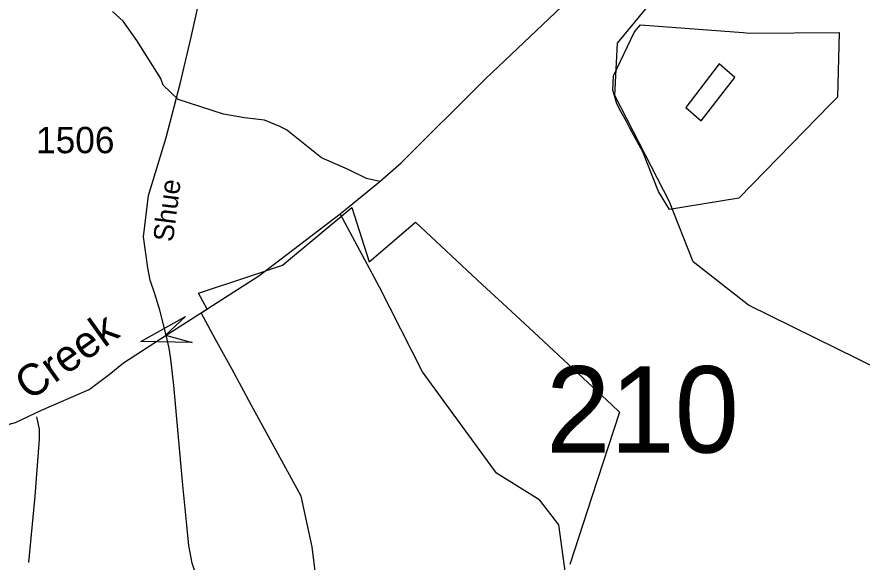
# Model space of a CAD drawing. Extents: x 1473865 to 1648260, y 639067 to 773536.
# Drawn here: x 1530604 to 1534612, y 672827 to 675414 of the extents above; entities that cross this region are included whole.
import ezdxf

# ---------------------------------------------------------------- set-up
doc = ezdxf.new("R2010")
doc.units = 0
for name, color, linetype in [('Exist Boundary Political City Limit New', 7, 'Continuous'), ('Exist Hydrographic Creek Single Shore', 7, 'Continuous'), ('Exist Hydrographic Creek Single Shore Label', 7, 'Continuous'), ('Exist Hydrographic Misc Water Feature', 7, 'Continuous'), ('Exist Road Secondary Structure Standard Bridge Attributed CELL', 7, 'Continuous'), ('Exist Road Secondary Structure Standard Bridge Number Label', 7, 'Continuous'), ('Exist Road Secondary Type 51 Attributed', 7, 'Continuous'), ('Exist Road Secondary Type 51 Label', 7, 'Continuous'), ('Exist Road Secondary Type 51 Number Label', 7, 'Continuous'), ('Map Preparation Boundary City Limit Buffer Line', 7, 'Continuous')]:
    doc.layers.add(name, color=color, linetype=linetype)

msp = doc.modelspace()

# ---------------------------------------------------------------- linework, layer by layer
at = {"layer": 'Exist Boundary Political City Limit New'}
for points in [[(1534047.8, 675339.3), (1534078, 675337.1), (1534503.1, 675340.2), (1534494.9, 675033), (1534462.8, 675000.2), (1534028.4, 674554), (1533698.5, 674499.2), (1533681.5, 674527.8), (1533646.9, 674585.9), (1533571.8, 674773.6), (1533511, 674885.8), (1533494.2, 674917), (1533468.6, 674965.2), (1533449.4, 675001.2), (1533439, 675034.2), (1533429.5, 675065.4), (1533433.9, 675133.3), (1533532.8, 675342.1), (1533560.8, 675376.4), (1534047.8, 675339.3)], [(1532025, 672732.6), (1532004, 672899.2), (1531952, 673140), (1531715.5, 673573.2), (1531622.6, 673743.5), (1531544.8, 673886.2), (1531477.8, 674009), (1531506, 674026.8), (1531464.4, 674102), (1531699.6, 674180.7), (1531862.9, 674235.2), (1532192.4, 674509.6), (1532203.5, 674474.8)], [(1532203.5, 674474.8), (1532274.9, 674251.9), (1532494.1, 674439.3), (1532812.6, 674142.9), (1532906.4, 674055.7), (1533054.9, 673917.5), (1533264.9, 673722), (1533425.1, 673572.8), (1533462, 673538.6), (1533330.9, 673135.7), (1533226.8, 672815.9)]]:
    msp.add_lwpolyline(points, dxfattribs=at)
at = {"layer": 'Exist Hydrographic Creek Single Shore'}
for points in [[(1532325.2, 674632.6), (1532425.5, 674721.4), (1532826.6, 675120.4), (1533307.6, 675577.9), (1533484, 675750.6), (1533742.1, 676058.2), (1534037.2, 676387.9), (1534170, 676555.2)], [(1530238.2, 673391.2), (1530597.9, 673489.3), (1530720.8, 673548.3), (1530946.5, 673646.2), (1531041.1, 673716.7), (1531109.6, 673772.1), (1531311.1, 673903.1), (1531751.2, 674184.6), (1532136.2, 674479.9), (1532325.2, 674632.6)]]:
    msp.add_lwpolyline(points, dxfattribs=at)
at = {"layer": 'Exist Hydrographic Misc Water Feature'}
for points in [[(1537083.2, 672908.5), (1536860.2, 673077.1), (1536521.3, 673215.2), (1536111.3, 673180.8), (1535912.3, 673250.5), (1535654.2, 673255.7), (1535306.3, 673403.9), (1535140.3, 673436.7), (1534802.2, 673686.4), (1534074.2, 674045.8), (1533811.2, 674251.4), (1533699.3, 674535.9), (1533440.2, 675040.1), (1533452.3, 675289.3), (1533690.2, 675579.9), (1533836.2, 675859.3), (1534016.3, 676141.3), (1534051.2, 676248.8), (1534170, 676555.2)], [(1532325.2, 674632.6), (1532261.6, 674646.1), (1532174.2, 674689.7), (1532048.1, 674744.8), (1531882.1, 674877.8), (1531850.4, 674894.1), (1531778.8, 674923.4), (1531683.1, 674934.4), (1531583.1, 674951.9), (1531368.2, 675022), (1531297.2, 675089), (1531285.7, 675121.3), (1531172.4, 675300.8), (1531108, 675394), (1531056.6, 675438.5)], [(1533933.8, 675190.9), (1533776.6, 674984), (1533849.6, 674920.2), (1534008.8, 675126.2), (1533933.8, 675190.9)], [(1534527.2, 669953.3), (1534191.2, 670360.5), (1533994.2, 670548.3), (1533913.2, 670697.7), (1533914.2, 670756.7), (1533889.1, 670780.2), (1533851.2, 670964.8), (1533819.2, 671034.4), (1533837.2, 671706.8), (1533806.2, 671792.9), (1533666.2, 671953.3), (1533621.2, 672236.4), (1533539.2, 672362.8), (1533424.2, 672447.2), (1533219.2, 672668), (1533174.2, 673003.7), (1533084.2, 673120.4), (1532878.2, 673249.4), (1532527.2, 673729.1), (1532323, 674130.5), (1532136.2, 674479.9)], [(1530696.2, 673515.7), (1530709.3, 673457.2), (1530708.6, 673409.6), (1530688.3, 673139.2), (1530659.3, 672825.5)]]:
    msp.add_lwpolyline(points, dxfattribs=at)
at = {"layer": 'Exist Road Secondary Structure Standard Bridge Attributed CELL'}
msp.add_lwpolyline([(1531434.6, 673869.4), (1531190.8, 673873.4), (1531403.9, 673991.8), (1531309, 673903)], close=True, dxfattribs=at)
at = {"layer": 'Exist Road Secondary Type 51 Attributed'}
for points in [[(1531311.1, 673903.1), (1531280.9, 674022.9), (1531258.7, 674099.5), (1531236.6, 674164), (1531225.5, 674222.4), (1531204, 674369.7), (1531228.2, 674566), (1531312, 674841.2), (1531378.8, 675096), (1531430.8, 675318.1), (1531472.1, 675503.4), (1531505, 675862.7), (1531510, 676122.2), (1531522.9, 676483.9), (1531544.7, 677173), (1531575.9, 677661.1), (1531589.4, 678148.9)], [(1531941.7, 672318.5), (1531768.5, 672446.4), (1531669.7, 672518.9), (1531588.1, 672581.4), (1531542.8, 672629.7), (1531488.3, 672697.3), (1531473.3, 672721.4), (1531458.2, 672751.6), (1531435, 672821.1), (1531418.5, 672905.3), (1531407.8, 673017.6), (1531390.7, 673191.9), (1531347.4, 673665.3), (1531334.3, 673789.2), (1531325.2, 673842.6), (1531311.1, 673903.1)]]:
    msp.add_lwpolyline(points, dxfattribs=at)
at = {"layer": 'Map Preparation Boundary City Limit Buffer Line'}
for points in [[(1534047.8, 675339.3), (1534078, 675337.1), (1534503.1, 675340.2), (1534494.9, 675033), (1534462.8, 675000.2), (1534028.4, 674554), (1533698.5, 674499.2), (1533681.5, 674527.8), (1533646.9, 674585.9), (1533571.8, 674773.6), (1533511, 674885.8), (1533494.2, 674917), (1533468.6, 674965.2), (1533449.4, 675001.2), (1533439, 675034.2), (1533429.5, 675065.4), (1533433.9, 675133.3), (1533532.8, 675342.1), (1533560.8, 675376.4), (1534047.8, 675339.3)], [(1532025, 672732.6), (1532004, 672899.2), (1531952, 673140), (1531715.5, 673573.2), (1531622.6, 673743.5), (1531544.8, 673886.2), (1531477.8, 674009), (1531506, 674026.8), (1531464.4, 674102), (1531699.6, 674180.7), (1531862.9, 674235.2), (1532192.4, 674509.6), (1532203.5, 674474.8)], [(1532203.5, 674474.8), (1532274.9, 674251.9), (1532494.1, 674439.3), (1532812.6, 674142.9), (1532906.4, 674055.7), (1533054.9, 673917.5), (1533264.9, 673722), (1533425.1, 673572.8), (1533462, 673538.6), (1533330.9, 673135.7), (1533226.8, 672815.9)]]:
    msp.add_lwpolyline(points, dxfattribs=at)

# ---------------------------------------------------------------- texts
at = {"layer": 'Exist Hydrographic Creek Single Shore Label'}
msp.add_text('Creek', height=150, rotation=35.5289, dxfattribs=at).set_placement((1530663.4, 673588.9))
at = {"layer": 'Exist Road Secondary Structure Standard Bridge Number Label'}
msp.add_text('210', height=410.1, dxfattribs=at).set_placement((1533113.3, 673346.2))
at = {"layer": 'Exist Road Secondary Type 51 Label'}
msp.add_text('Shue', height=95, rotation=82.7016, dxfattribs=at).set_placement((1531343.8, 674342.8))
at = {"layer": 'Exist Road Secondary Type 51 Number Label'}
msp.add_text('1506', height=125, dxfattribs=at).set_placement((1530694.7, 674766.8))

doc.saveas('drawing.dxf')
